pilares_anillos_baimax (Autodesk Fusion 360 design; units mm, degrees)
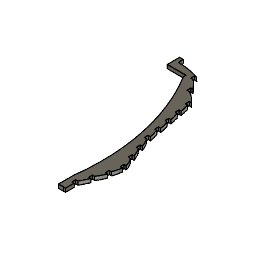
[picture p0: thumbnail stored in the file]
part number: 2026-07-18-00-39-35-033
parameter "d_1" = 112
parameter "d_1_int" = 108.5 (= "d_1 - 3.5 mm")
parameter "h_1" = -10
parameter "d_2" = 108.5
parameter "d_2_int" = 105 (= "d_2 - 3.5 mm")
parameter "h_2" = 10
parameter "h_3" = -20
parameter "h_4" = 20
parameter "h_5" = -30
parameter "h_6" = 30
parameter "h_7" = 40
parameter "d_3" = 105 (= "d_2_int")
parameter "d_3_int" = 101.5 (= "d_3 - 3.5 mm")
parameter "d_4" = 101.5 (= "d_3_int")
parameter "d_4_int" = 98 (= "d_4 - 3.5 mm")
parameter "d_5" = 98 (= "d_4_int")
parameter "d_5_int" = 94.5 (= "d_5 - 3.5 mm")
parameter "d_6" = 94.5 (= "d_5_int")
parameter "d_6_int" = 91 (= "d_6 - 3.5 mm")
parameter "d_7" = 91 (= "d_6_int")
parameter "d_7_int" = 87.5 (= "d_7 - 3.5 mm")
parameter "d_8" = 87.5 (= "d_7_int")
parameter "d_8_int" = 84 (= "d_8 - 3.5 mm")
parameter "h_8" = 50
parameter "h_9" = 60
parameter "h_10" = 70
parameter "h_11" = 110
parameter "h_12" = 120
parameter "h_13" = 130
parameter "h_14" = 140
parameter "h_15" = 80
parameter "d_9" = 84 (= "d_8_int")
parameter "d_9_int" = 80.5 (= "d_9 - 3.5 mm")
parameter "d_10" = 80.5 (= "d_9_int")
parameter "d_10_int" = 77 (= "d_10 - 3.5 mm")
parameter "d_11" = 77 (= "d_10_int")
parameter "d_11_int" = 73.5 (= "d_11 - 3.5 mm")
parameter "d_12" = 73.5 (= "d_11_int")
parameter "d_12_int" = 70 (= "d_12 - 3.5 mm")
parameter "d_13" = 70 (= "d_12_int")
parameter "d_13_int" = 66.5 (= "d_13 - 3.5 mm")
parameter "d_14" = 66.5 (= "d_13_int")
parameter "d_14_int" = 63 (= "d_14 - 3.5 mm")
parameter "d_15" = 63 (= "d_14_int")
parameter "d_15_int" = 59.5 (= "d_15 - 3.5 mm")
parameter "d_16" = 59.5 (= "d_15_int")
parameter "d_16_int" = 56 (= "d_16 - 3.5 mm")
parameter "h_16" = 160
parameter "h_17" = 170
parameter "h_18" = 180
parameter "h_19" = 90
parameter "h_20" = 200
parameter "d_17" = 56 (= "d_16_int")
parameter "d_17_int" = 52.5 (= "d_17 - 3.5 mm")
parameter "d_18" = 52.5 (= "d_17_int")
parameter "d_18_int" = 49 (= "d_18 - 3.5 mm")
parameter "d_19" = 49 (= "d_18_int")
parameter "d_19_int" = 45.5 (= "d_19 - 3.5 mm")
parameter "d_20" = 45.5 (= "d_19_int")
parameter "d_20_int" = 42 (= "d_20 - 3.5 mm")
parameter "d_21" = 42 (= "d_20_int")
parameter "d_21_int" = 38.5 (= "d_21 - 3.5 mm")
parameter "h_21" = 210
parameter "h_22" = 220
parameter "h_23" = 295
parameter "h_24" = 295
parameter "h_25" = 300
parameter "h_26" = 290
parameter "h_27" = 305
parameter "h_28" = 285
parameter "d_22" = 38.5 (= "d_21_int")
parameter "d_22_int" = 35 (= "d_22 - 3.5 mm")
parameter "d_23" = 35 (= "d_22_int")
parameter "d_23_int" = 31.5 (= "d_23 - 3.5 mm")
parameter "d_24" = 31.5 (= "d_23_int")
parameter "d_24_int" = 28 (= "d_24 - 3.5 mm")
parameter "d_25" = 28 (= "d_24_int")
parameter "d_25_int" = 24.5 (= "d_25 - 3.5 mm")
parameter "d_26" = 24.5 (= "d_25_int")
parameter "d_26_int" = 21 (= "d_26 - 3.5 mm")
parameter "d_27" = 21 (= "d_26_int")
parameter "d_27_int" = 17.5 (= "d_27 - 3.5 mm")
parameter "d_28" = 17.5 (= "d_27_int")
parameter "d_28_int" = 14 (= "d_28 - 3.5 mm")
parameter "d_29" = 14 (= "d_28_int")
parameter "d_29_int" = 10.5 (= "d_29 - 3.5 mm")
sketch "Boceto1" plane through (0, 0, 0) normal (0, 1, 0) x axis (1, 0, 0)
  circle C1 centre (0, 0) radius 56
  circle C2 centre (0, 0) radius 54.25
  point P1 (0, 0)
  point P2 (0, 0)
  coincident P1 P2
  concentric C1 C2
  dimension "d1" diameter C1 = 112 (= "d_1")
  dimension "d2" diameter C2 = 108.5 (= "d_1_int")
work_plane "PlanoDeObra2" AlongDistance -10 (= "h_1")
sketch "Boceto3" plane through (0, -10, 0) normal (0, 1, 0) x axis (1, 0, 0)
  circle C1 centre (0, 0) radius 54.25
  circle C2 centre (0, 0) radius 52.5
  point P1 (0, 0)
  point P2 (0, 0)
  coincident P1 P2
  concentric C1 C2
  dimension "d12" diameter C2 = 105 (= "d_2_int")
  dimension "d13" diameter C1 = 108.5 (= "d_2")
work_plane "PlanoDeObra3" AlongDistance 0
work_plane "PlanoDeObra4" AlongDistance 10 (= "h_2")
sketch "Boceto4" plane through (0, 10, 0) normal (0, 1, 0) x axis (1, 0, 0)
  circle C1 centre (0, 0) radius 52.5
  circle C2 centre (0, 0) radius 50.75
  point P1 (0, 0)
  point P2 (0, 0)
  point P3 (0, 0)
  coincident P1 P2
  coincident P1 P3
  dimension "d26" diameter C1 = 105 (= "d_3")
  dimension "d27" diameter C2 = 101.5 (= "d_3_int")
work_plane "PlanoDeObra5" AlongDistance -20 (= "h_3")
sketch "Boceto5" plane through (0, -20, 0) normal (0, 1, 0) x axis (1, 0, 0)
  circle C1 centre (0, 0) radius 50.75
  circle C2 centre (0, 0) radius 49
  point P1 (0, 0)
  point P2 (0, 0)
  point P3 (0, 0)
  coincident P1 P2
  coincident P1 P3
  dimension "d41" diameter C1 = 101.5 (= "d_4")
  dimension "d42" diameter C2 = 98 (= "d_4_int")
work_plane "PlanoDeObra6" AlongDistance 20 (= "h_4")
sketch "Boceto6" plane through (0, 20, 0) normal (0, 1, 0) x axis (1, 0, 0)
  circle C1 centre (0, 0) radius 49
  circle C2 centre (0, 0) radius 47.25
  point P1 (0, 0)
  point P2 (0, 0)
  coincident P1 P2
  concentric C1 C2
  dimension "d46" diameter C1 = 98 (= "d_5")
  dimension "d47" diameter C2 = 94.5 (= "d_5_int")
work_plane "PlanoDeObra7" AlongDistance -30 (= "h_5")
sketch "Boceto7" plane through (0, -30, 0) normal (0, 1, 0) x axis (1, 0, 0)
  circle C1 centre (0, 0) radius 47.25
  circle C2 centre (0, 0) radius 45.5
  point P1 (0, 0)
  point P2 (0, 0)
  coincident P1 P2
  concentric C1 C2
  dimension "d51" diameter C1 = 94.5 (= "d_6")
  dimension "d52" diameter C2 = 91 (= "d_6_int")
work_plane "PlanoDeObra8" AlongDistance 30 (= "h_6")
sketch "Boceto9" plane through (0, 30, 0) normal (0, 1, 0) x axis (1, 0, 0)
  circle C1 centre (0, 0) radius 45.5
  circle C2 centre (0, 0) radius 43.75
  point P1 (0, 0)
  point P2 (0, 0)
  point P3 (0, 0)
  coincident P1 P2
  coincident P1 P3
  dimension "d56" diameter C1 = 91 (= "d_7")
  dimension "d57" diameter C2 = 87.5 (= "d_7_int")
work_plane "PlanoDeObra9" AlongDistance 40 (= "h_7")
sketch "Boceto10" plane through (0, 40, 0) normal (0, 1, 0) x axis (1, 0, 0)
  circle C1 centre (0, 0) radius 43.75
  circle C2 centre (0, 0) radius 42
  point P1 (0, 0)
  point P2 (0, 0)
  coincident P1 P2
  concentric C1 C2
  dimension "d61" diameter C1 = 87.5 (= "d_8")
  dimension "d62" diameter C2 = 84 (= "d_8_int")
work_plane "PlanoDeObra10" AlongDistance 50 (= "h_8")
sketch "Boceto11" plane through (0, 50, 0) normal (0, 1, 0) x axis (1, 0, 0)
  circle C1 centre (0, 0) radius 42
  circle C2 centre (0, 0) radius 40.25
  point P1 (0, 0)
  point P2 (0, 0)
  coincident P1 P2
  concentric C1 C2
  dimension "d90" diameter C1 = 84 (= "d_9")
  dimension "d91" diameter C2 = 80.5 (= "d_9_int")
work_plane "PlanoDeObra11" AlongDistance 60 (= "h_9")
sketch "Boceto12" plane through (0, 60, 0) normal (0, 1, 0) x axis (1, 0, 0)
  circle C1 centre (0, 0) radius 40.25
  circle C2 centre (0, 0) radius 38.5
  point P1 (0, 0)
  point P2 (0, 0)
  point P3 (0, 0)
  coincident P1 P2
  coincident P1 P3
  dimension "d95" diameter C1 = 80.5 (= "d_10")
  dimension "d96" diameter C2 = 77 (= "d_10_int")
work_plane "PlanoDeObra12" AlongDistance 70 (= "h_10")
sketch "Boceto13" plane through (0, 70, 0) normal (0, 1, 0) x axis (1, 0, 0)
  circle C1 centre (0, 0) radius 38.5
  circle C2 centre (0, 0) radius 36.75
  point P1 (0, 0)
  point P2 (0, 0)
  point P3 (0, 0)
  coincident P1 P2
  coincident P1 P3
  dimension "d100" diameter C1 = 77 (= "d_11")
  dimension "d101" diameter C2 = 73.5 (= "d_11_int")
work_plane "PlanoDeObra13" AlongDistance 110 (= "h_11")
sketch "Boceto14" plane through (0, 110, 0) normal (0, 1, 0) x axis (1, 0, 0)
  circle C1 centre (0, 0) radius 36.75
  circle C2 centre (0, 0) radius 35
  point P1 (0, 0)
  point P2 (0, 0)
  coincident P1 P2
  concentric C1 C2
  dimension "d105" diameter C1 = 73.5 (= "d_12")
  dimension "d106" diameter C2 = 70 (= "d_12_int")
work_plane "PlanoDeObra14" AlongDistance 120 (= "h_12")
sketch "Boceto15" plane through (0, 120, 0) normal (0, 1, 0) x axis (1, 0, 0)
  circle C1 centre (0, 0) radius 35
  circle C2 centre (0, 0) radius 33.25
  point P1 (0, 0)
  point P2 (0, 0)
  coincident P1 P2
  concentric C1 C2
  dimension "d110" diameter C1 = 70 (= "d_13")
  dimension "d111" diameter C2 = 66.5 (= "d_13_int")
work_plane "PlanoDeObra15" AlongDistance 130 (= "h_13")
sketch "Boceto16" plane through (0, 130, 0) normal (0, 1, 0) x axis (1, 0, 0)
  circle C1 centre (0, 0) radius 33.25
  circle C2 centre (0, 0) radius 31.5
  point P1 (0, 0)
  point P2 (0, 0)
  coincident P1 P2
  concentric C1 C2
  dimension "d115" diameter C1 = 66.5 (= "d_14")
  dimension "d116" diameter C2 = 63 (= "d_14_int")
work_plane "PlanoDeObra17" AlongDistance 140 (= "h_14")
sketch "Boceto17" plane through (0, 140, 0) normal (0, 1, 0) x axis (1, 0, 0)
  circle C1 centre (0, 0) radius 31.5
  circle C2 centre (0, 0) radius 29.75
  point P1 (0, 0)
  point P2 (0, 0)
  point P3 (0, 0)
  coincident P1 P2
  coincident P1 P3
  dimension "d121" diameter C1 = 63 (= "d_15")
  dimension "d122" diameter C2 = 59.5 (= "d_15_int")
work_plane "PlanoDeObra18" AlongDistance 80 (= "h_15")
sketch "Boceto18" plane through (0, 80, 0) normal (0, 1, 0) x axis (1, 0, 0)
  circle C1 centre (0, 0) radius 29.75
  circle C2 centre (0, 0) radius 28
  point P1 (0, 0)
  point P2 (0, 0)
  point P3 (0, 0)
  coincident P1 P2
  coincident P1 P3
  dimension "d126" diameter C1 = 59.5 (= "d_16")
  dimension "d127" diameter C2 = 56 (= "d_16_int")
work_plane "PlanoDeObra19" AlongDistance 160 (= "h_16")
sketch "Boceto19" plane through (0, 160, 0) normal (0, 1, 0) x axis (1, 0, 0)
  circle C1 centre (0, 0) radius 28
  circle C2 centre (0, 0) radius 26.25
  point P1 (0, 0)
  point P2 (0, 0)
  coincident P1 P2
  concentric C1 C2
  dimension "d162" diameter C1 = 56 (= "d_17")
  dimension "d163" diameter C2 = 52.5 (= "d_17_int")
work_plane "PlanoDeObra20" AlongDistance 170 (= "h_17")
sketch "Boceto20" plane through (0, 170, 0) normal (0, 1, 0) x axis (1, 0, 0)
  circle C1 centre (0, 0) radius 26.25
  circle C2 centre (0, 0) radius 24.5
  point P1 (0, 0)
  point P2 (0, 0)
  coincident P1 P2
  concentric C1 C2
  dimension "d167" diameter C1 = 52.5 (= "d_18")
  dimension "d168" diameter C2 = 49 (= "d_18_int")
work_plane "PlanoDeObra21" AlongDistance 180 (= "h_18")
sketch "Boceto21" plane through (0, 180, 0) normal (0, 1, 0) x axis (1, 0, 0)
  circle C1 centre (0, 0) radius 24.5
  circle C2 centre (0, 0) radius 22.75
  point P1 (0, 0)
  point P2 (0, 0)
  point P3 (0, 0)
  coincident P1 P2
  coincident P1 P3
  dimension "d172" diameter C1 = 49 (= "d_19")
  dimension "d173" diameter C2 = 45.5 (= "d_19_int")
work_plane "PlanoDeObra22" AlongDistance 90 (= "h_19")
sketch "Boceto22" plane through (0, 90, 0) normal (0, 1, 0) x axis (1, 0, 0)
  circle C1 centre (0, 0) radius 22.75
  circle C2 centre (0, 0) radius 21
  point P1 (0, 0)
  point P2 (0, 0)
  point P3 (0, 0)
  coincident P1 P2
  coincident P1 P3
  dimension "d177" diameter C1 = 45.5 (= "d_20")
  dimension "d178" diameter C2 = 42 (= "d_20_int")
work_plane "PlanoDeObra24" AlongDistance 200 (= "h_20")
sketch "Boceto24" plane through (0, 200, 0) normal (0, 1, 0) x axis (1, 0, 0)
  circle C1 centre (0, 0) radius 21
  circle C2 centre (0, 0) radius 19.25
  point P1 (0, 0)
  point P2 (0, 0)
  point P3 (0, 0)
  coincident P1 P2
  coincident P1 P3
  dimension "d187" diameter C1 = 42 (= "d_21")
  dimension "d188" diameter C2 = 38.5 (= "d_21_int")
work_plane "PlanoDeObra25" AlongDistance 210 (= "h_21")
sketch "Boceto25" plane through (0, 210, 0) normal (0, 1, 0) x axis (1, 0, 0)
  circle C1 centre (0, 0) radius 19.25
  circle C2 centre (0, 0) radius 17.5
  point P1 (0, 0)
  point P2 (0, 0)
  coincident P1 P2
  concentric C1 C2
  dimension "d220" diameter C1 = 38.5 (= "d_22")
  dimension "d221" diameter C2 = 35 (= "d_22_int")
work_plane "PlanoDeObra26" AlongDistance 220 (= "h_22")
sketch "Boceto26" plane through (0, 220, 0) normal (0, 1, 0) x axis (1, 0, 0)
  circle C1 centre (0, 0) radius 17.5
  circle C2 centre (0, 0) radius 15.75
  point P1 (0, 0)
  point P2 (0, 0)
  coincident P1 P2
  concentric C1 C2
  dimension "d225" diameter C1 = 35 (= "d_23")
  dimension "d226" diameter C2 = 31.5 (= "d_23_int")
work_plane "PlanoDeObra28" AlongDistance 295 (= "h_23")
sketch "Boceto27" plane through (0, 295, 0) normal (0, 1, 0) x axis (1, 0, 0)
  circle C1 centre (0, 0) radius 15.75
  circle C2 centre (0, 0) radius 14
  point P1 (0, 0)
  point P2 (0, 0)
  coincident P1 P2
  concentric C1 C2
  dimension "d231" diameter C1 = 31.5 (= "d_24")
  dimension "d232" diameter C2 = 28 (= "d_24_int")
work_plane "PlanoDeObra29" AlongDistance 295 (= "h_24")
sketch "Boceto28" plane through (0, 295, 0) normal (0, 1, 0) x axis (1, 0, 0)
  circle C1 centre (0, 0) radius 14
  circle C2 centre (0, 0) radius 12.25
  point P1 (0, 0)
  point P2 (0, 0)
  point P3 (0, 0)
  coincident P1 P2
  coincident P1 P3
  dimension "d236" diameter C1 = 28 (= "d_25")
  dimension "d237" diameter C2 = 24.5 (= "d_25_int")
work_plane "PlanoDeObra30" AlongDistance 300 (= "h_25")
sketch "Boceto29" plane through (0, 300, 0) normal (0, 1, 0) x axis (1, 0, 0)
  circle C1 centre (0, 0) radius 12.25
  circle C2 centre (0, 0) radius 10.5
  point P1 (0, 0)
  point P2 (0, 0)
  coincident P1 P2
  concentric C1 C2
  dimension "d241" diameter C1 = 24.5 (= "d_26")
  dimension "d242" diameter C2 = 21 (= "d_26_int")
work_plane "PlanoDeObra31" AlongDistance 290 (= "h_26")
sketch "Boceto30" plane through (0, 290, 0) normal (0, 1, 0) x axis (1, 0, 0)
  circle C1 centre (0, 0) radius 10.5
  circle C2 centre (0, 0) radius 8.75
  point P1 (0, 0)
  point P2 (0, 0)
  point P3 (0, 0)
  coincident P1 P2
  coincident P1 P3
  dimension "d246" diameter C1 = 21 (= "d_27")
  dimension "d247" diameter C2 = 17.5 (= "d_27_int")
work_plane "PlanoDeObra32" AlongDistance 305 (= "h_27")
sketch "Boceto31" plane through (0, 305, 0) normal (0, 1, 0) x axis (1, 0, 0)
  circle C1 centre (0, 0) radius 8.75
  circle C2 centre (0, 0) radius 7
  point P1 (0, 0)
  point P2 (0, 0)
  coincident P1 P2
  concentric C1 C2
  dimension "d251" diameter C1 = 17.5 (= "d_28")
  dimension "d252" diameter C2 = 14 (= "d_28_int")
work_plane "PlanoDeObra33" AlongDistance 285 (= "h_28")
sketch "Boceto32" plane through (0, 285, 0) normal (0, 1, 0) x axis (1, 0, 0)
  circle C1 centre (0, 0) radius 7
  circle C2 centre (0, 0) radius 5.25
  point P1 (0, 0)
  point P2 (0, 0)
  coincident P1 P2
  concentric C1 C2
  dimension "d256" diameter C1 = 14 (= "d_29")
  dimension "d257" diameter C2 = 10.5 (= "d_29_int")
sketch "Boceto33" plane through (0, 0, 0) normal (0, 0, 1) x axis (1, 0, 0)
  line L1 (47.25, -30) -> (45.5, -30)
  line L2 (45.5, -27) -> (47.25, -27)
  line L3 (50.75, -20) -> (49, -20)
  line L4 (49, -17) -> (50.75, -17)
  line L5 (54.25, -10) -> (52.5, -10)
  line L6 (52.5, -7) -> (54.25, -7)
  line L7 (56, 0) -> (54.25, 0)
  line L8 (54.25, 3) -> (56, 3)
  line L9 (52.5, 10) -> (50.75, 10)
  line L10 (50.75, 13) -> (52.5, 13)
  line L11 (49, 20) -> (47.25, 20)
  line L12 (47.25, 23) -> (49, 23)
  line L13 (45.5, 30) -> (43.75, 30)
  line L14 (43.75, 33) -> (45.5, 33)
  line L15 (43.75, 40) -> (42, 40)
  line L16 (42, 43) -> (43.75, 43)
  line L17 (42, 50) -> (40.25, 50)
  line L18 (40.25, 53) -> (42, 53)
  line L19 (40.25, 60) -> (38.5, 60)
  line L20 (38.5, 63) -> (40.25, 63)
  line L21 (38.5, 70) -> (36.75, 70)
  line L22 (36.75, 73) -> (38.5, 73)
  line L23 (29.75, 80) -> (28, 80)
  line L24 (28, 83) -> (29.75, 83)
  line L25 (22.75, 90) -> (21, 90)
  line L26 (21, 93) -> (22.75, 93)
  line L27 (45.5, -30) -> (47.25, -30)
  line L28 (45.5, -27) -> (45.5, -30)
  line L29 (49, -20) -> (50.75, -20)
  line L30 (49, -17) -> (49, -20)
  line L31 (50.75, -17) -> (49, -17)
  line L32 (52.5, -10) -> (54.25, -10)
  line L33 (52.5, -10) -> (54.25, -10)
  line L34 (52.5, -7) -> (52.5, -10)
  line L35 (54.25, 0) -> (56, 0)
  line L36 (54.25, 0) -> (56, 0)
  line L37 (54.25, 3) -> (54.25, 0)
  line L38 (50.75, 10) -> (52.5, 10)
  line L39 (50.75, 13) -> (50.75, 10)
  line L40 (47.25, 20) -> (49, 20)
  line L41 (43.75, 30) -> (45.5, 30)
  line L42 (43.75, 33) -> (43.75, 30)
  line L43 (42, 40) -> (43.75, 40)
  line L44 (42, 43) -> (42, 40)
  line L45 (40.25, 50) -> (42, 50)
  line L46 (38.5, 60) -> (40.25, 60)
  line L47 (38.5, 63) -> (40.25, 63)
  line L48 (36.75, 70) -> (38.5, 70)
  line L49 (36.75, 73) -> (36.75, 70)
  line L50 (38.5, 60) -> (38.5, 63)
  line L51 (40.25, 53) -> (40.25, 50)
  line L52 (38.5, 73) -> (36.75, 75)
  line L53 (28, 80) -> (29.75, 80)
  line L54 (29.75, 83) -> (28, 85)
  line L55 (21, 90) -> (22.75, 90)
  line L56 (21, 93) -> (21, 90)
  line L57 (28, 83) -> (28, 80)
  line L58 (47.25, 23) -> (47.25, 20)
  line L59 (17, 88) -> (17, 90)
  line L60 (41.5, -32) -> (41.5, -25)
  line L61 (2, 90) -> (2, 95)
  line L62 (17, 90) -> (2, 90)
  line L63 (2, 100) -> (2, 95)
  line L64 (5, 100) -> (2, 100)
  line L65 (5, 96) -> (5, 100)
  line L66 (41.5, -37) -> (41.5, -32)
  line L67 (44.5, -37) -> (41.5, -37)
  line L68 (45.5, -37) -> (44.5, -37)
  line L69 (47.25, -38.2302) -> (47.25, -30)
  line L70 (47.25, -37) -> (45.5, -37)
  arc A1 centre (-131.6173, -3.3783) radius 174.4624 clockwise from (17, 88) to (41.5, -25)
  arc A2 centre (-12.1249, 48.1252) radius 54.4955 clockwise from (22.75, 90) to (29.75, 83)
  arc A3 centre (19.2917, 57.9584) radius 24.3969 clockwise from (29.75, 80) to (38.5, 73)
  arc A4 centre (-26.7489, 49.969) radius 68.2544 clockwise from (38.5, 70) to (40.25, 63)
  arc A5 centre (-76.2927, 27.1457) radius 121.0852 clockwise from (40.25, 60) to (42, 53)
  arc A6 centre (22.875, 41.5) radius 20.9289 clockwise from (42, 50) to (43.75, 43)
  arc A7 centre (-1.5, 24.9688) radius 47.6812 clockwise from (43.75, 40) to (45.5, 33)
  arc A8 centre (19.0393, 12.3947) radius 31.7823 clockwise from (45.5, 30) to (49, 23)
  arc A9 centre (-15.6248, -16.6874) radius 74.3124 clockwise from (49, 20) to (52.5, 13)
  arc A10 centre (40.625, -0.3125) radius 15.7278 clockwise from (52.5, 10) to (56, 3)
  arc A11 centre (21.7396, 4.8464) radius 34.6015 clockwise from (56, 0) to (54.25, -7)
  arc A12 centre (24.9327, 0.2836) radius 31.0686 clockwise from (54.25, -10) to (50.75, -17)
  arc A13 centre (-15.8334, 8.9167) radius 72.5915 clockwise from (50.75, -20) to (47.25, -27)
  arc A14 centre (4.1403, 36.9029) radius 59.1033 clockwise from (5, 96) to (22.75, 93)
  point P52 (28, 85)
  point P50 (36.75, 75)
  point P84 (47.25, -37)
  point P2 (47.25, -30)
  point P3 (47.25, -27)
  point P28 (45.5, -30)
  point P8 (56, 0)
  point P35 (54.25, 0)
  point P10 (52.5, 10)
  point P37 (50.75, 10)
  point P12 (49, 20)
  point P39 (47.25, 20)
  point P14 (45.5, 30)
  point P40 (43.75, 30)
  point P18 (42, 50)
  point P44 (40.25, 50)
  point P22 (38.5, 70)
  point P47 (36.75, 70)
  horizontal L1
  perpendicular L2 L28
  perpendicular L4 L30
  perpendicular L6 L34
  perpendicular L8 L37
  perpendicular L10 L39
  perpendicular L14 L42
  perpendicular L16 L44
  perpendicular L22 L49
  perpendicular L19 L50
  perpendicular L18 L51
  perpendicular L26 L56
  perpendicular L24 L57
  perpendicular L12 L58
  coincident P52 A2
  coincident P50 A3
  perpendicular L59 L62
  perpendicular L63 L64
  perpendicular L66 L67
  perpendicular L27 L69
  coincident L69 P84
  perpendicular L69 L70
  dimension "d262" distance P2 P3 = 3
  dimension "d263" distance P2 P28 = 1.75
  dimension "d272" distance P8 P35 = 1.75
  dimension "d275" distance P10 P37 = 1.75
  dimension "d280" distance P12 P39 = 1.75
  dimension "d285" distance P14 P40 = 1.75
  dimension "d288" distance P18 P44 = 1.75
  dimension "d291" distance P22 P47 = 1.75
sketch "Boceto34" plane through (0, 93, 0) normal (0, 1, 0) x axis (-1, 0, 0)
  line L1 (-185, 110) -> (-160, 110)
  line L2 (-160, 85) -> (-160, 110)
  line L3 (-135, 110) -> (-160, 110)
  line L4 (-160, 135) -> (-160, 110)
  line L5 (-184.8747, 107.5) -> (-160, 107.5)
  line L6 (-184.8747, 112.5) -> (-160, 112.5)
  line L7 (-162.5, 85.1253) -> (-162.5, 110)
  line L8 (-157.5, 85.1253) -> (-157.5, 110)
  line L9 (-135.1253, 107.5) -> (-160, 107.5)
  line L10 (-135.1253, 112.5) -> (-160, 112.5)
  line L11 (-162.5, 134.8747) -> (-162.5, 110)
  line L12 (-157.5, 134.8747) -> (-157.5, 110)
  circle C1 centre (-160, 110) radius 21
  circle C2 centre (-160, 110) radius 22.75
  circle C3 centre (-160, 110) radius 21
  circle C4 centre (-160, 110) radius 2.5
  circle C5 centre (-160, 110) radius 22.75
  circle C6 centre (-160, 110) radius 25
  point P6 (-160, 110)
  point P7 (-160, 110)
  point P8 (-185, 110)
  point P3 (-160, 110)
  point P9 (-160, 110)
  point P10 (-160, 85)
  point P5 (-160, 110)
  point P11 (-160, 110)
  point P12 (-135, 110)
  point P13 (-160, 135)
  point P14 (-160, 107.5)
  point P15 (-184.8747, 107.5)
  point P16 (-160, 112.5)
  point P17 (-184.8747, 112.5)
  point P18 (-162.5, 110)
  point P19 (-162.5, 85.1253)
  point P20 (-157.5, 110)
  point P21 (-157.5, 85.1253)
  point P22 (-135.1253, 107.5)
  point P23 (-135.1253, 112.5)
  point P24 (-162.5, 134.8747)
  point P25 (-157.5, 134.8747)
  tangent C1 C3
  concentric C3 C4
  concentric C4 C5
  concentric C4 C6
  coincident P6 P7
  coincident C6 P8
  horizontal L1
  coincident P3 P9
  coincident C6 P10
  perpendicular L1 L2
  coincident P5 P11
  coincident C6 P12
  perpendicular L2 L3
  coincident C6 P13
  perpendicular L3 L4
  coincident C4 P14
  coincident L2 P14
  coincident C6 P15
  tangent C4 L5
  coincident C4 P16
  coincident L4 P16
  coincident C6 P17
  tangent C4 L6
  coincident C4 P18
  coincident L1 P18
  coincident C6 P19
  tangent C4 L7
  coincident C4 P20
  coincident L3 P20
  coincident C6 P21
  tangent C4 L8
  coincident C6 P22
  horizontal L9
  coincident C6 P23
  parallel L9 L10
  coincident C6 P24
  perpendicular L10 L11
  coincident C6 P25
  vertical L12
  dimension "d294" diameter C4 = 5
  dimension "d297" diameter C6 = 50
extrude "Extruir" new body sketch "Boceto33" along normal blind 3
